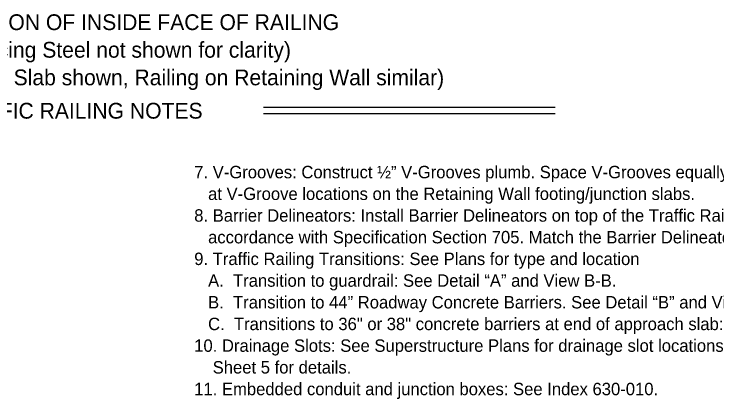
# Model space of a CAD drawing. Extents: x 0.5 to 40.8, y 1 to 25.8.
# Drawn here: x 18.01 to 29.41, y 3.12 to 9.36 of the extents above; entities that cross this region are included whole.
import ezdxf

# ---------------------------------------------------------------- set-up
doc = ezdxf.new("R2010")
doc.units = 0
doc.layers.add('Dimension', color=7, linetype='Continuous')
doc.layers.add('TextStructures', color=7, linetype='Continuous')

msp = doc.modelspace()

# ---------------------------------------------------------------- linework, layer by layer
at = {"layer": 'Dimension'}
for p, q in [((22.053, 7.849), (26.784, 7.849)), ((22.053, 7.746), (26.784, 7.746))]:
    msp.add_line(p, q, dxfattribs=at)

# ---------------------------------------------------------------- texts
for s, p in [('ELEVATION OF INSIDE FACE OF RAILING', (16.506, 9.101)), ('(Reinforcing Steel not shown for clarity)', (16.523, 8.653)), ('(Railing on Bridge Deck and Approach Slab shown, Railing on Retaining Wall similar)', (12.081, 8.205))]:
    msp.add_text(s, height=0.256, dxfattribs=at).set_placement(p)
at = {"layer": 'TextStructures'}
for s, height, p in [('TRAFFIC RAILING NOTES', 0.256, (16.88, 7.664)), ('7. V-Grooves: Construct ½” V-Grooves plumb. Space V-Grooves equally between ¾” Open Joints and/or Deck Joints and the', 0.2016, (20.928, 6.696)), ('   at V-Groove locations on the Retaining Wall footing/junction slabs. ', 0.2016, (20.928, 6.344)), ('8. Barrier Delineators: Install Barrier Delineators on top of the Traffic Railing 2” from the face of the traffic side in', 0.2016, (20.928, 5.992)), ('   accordance with Specification Section 705. Match the Barrier Delineator to the color (white or yellow) of the near edgeline.', 0.2016, (20.928, 5.64)), ('9. Traffic Railing Transitions: See Plans for type and location', 0.2016, (20.928, 5.288)), ('   A.  Transition to guardrail: See Detail “A” and View B-B.', 0.2016, (20.928, 4.936)), ('   B.  Transition to 44” Roadway Concrete Barriers. See Detail “B” and View C-C.', 0.2016, (20.928, 4.584)), ('   C.  Transitions to 36" or 38" concrete barriers at end of approach slab: See Detail "C", View D-D and Section E-E.', 0.2016, (20.928, 4.232)), ('10. Drainage Slots: See Superstructure Plans for drainage slot locations and size (if required). See Index 521-427', 0.2016, (20.928, 3.88)), ('    Sheet 5 for details.', 0.2016, (20.928, 3.528)), ('11. Embedded conduit and junction boxes: See Index 630-010.', 0.2016, (20.928, 3.176))]:
    msp.add_text(s, height=height, dxfattribs=at).set_placement(p)

doc.saveas('drawing.dxf')
